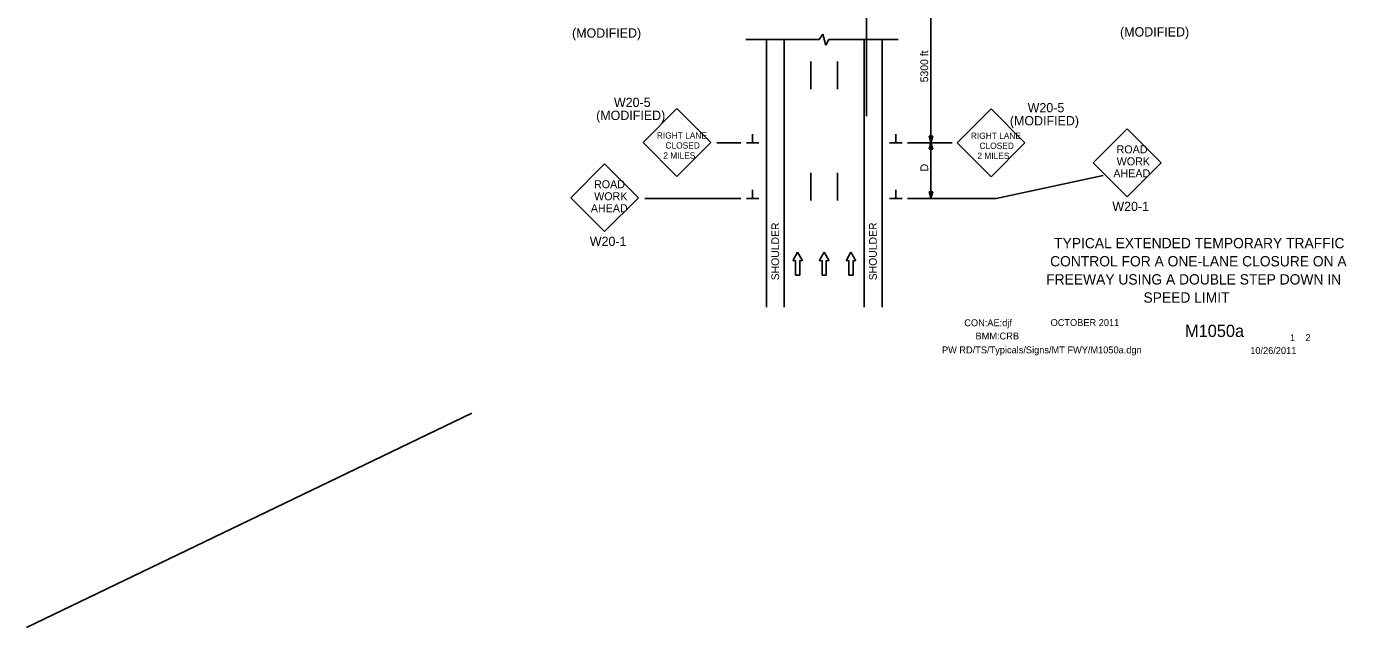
# Model space of a CAD drawing. Extents: x 16247 to 18479, y 5687 to 6964.
# Drawn here: x 16247 to 17435, y 5687 to 6228 of the extents above; entities that cross this region are included whole.
import ezdxf

# ---------------------------------------------------------------- set-up
doc = ezdxf.new("R2010")
doc.units = 0
for name, color, linetype in [('ALI_LEGAL_EX', 7, 'Continuous'), ('BORDER', 7, 'Continuous'), ('BORDER_SIGNAL_WO', 7, 'Continuous'), ('MT_SCRATCH_LEVEL_E', 7, 'Continuous'), ('PAVT_EDGE_EX', 7, 'Continuous'), ('TRAFFIC_SIGNS_PR', 7, 'Continuous'), ('TYPICAL_TEXT_DIMEN_PR', 7, 'Continuous')]:
    doc.layers.add(name, color=color, linetype=linetype)

msp = doc.modelspace()

# ---------------------------------------------------------------- linework, layer by layer
at = {"layer": 'ALI_LEGAL_EX'}
msp.add_line((17002.7, 6964.1), (17002.7, 6147.1), dxfattribs=at)
for points in [[(16952.7, 6196.2), (16952.7, 6171.2)], [(16976.7, 6196.2), (16976.7, 6171.2)], [(16952.7, 6096.2), (16952.7, 6071.2)], [(16976.7, 6096.2), (16976.7, 6071.2)]]:
    msp.add_lwpolyline(points, dxfattribs=at)
at = {"layer": 'MT_SCRATCH_LEVEL_E'}
for p, q in [((16940.7, 6024.8), (16936.6, 6017.6)), ((16944.9, 6017.6), (16940.7, 6024.8)), ((16964.6, 6024.8), (16960.5, 6017.6)), ((16968.8, 6017.6), (16964.6, 6024.8)), ((16988.7, 6024.8), (16984.6, 6017.6)), ((16992.8, 6017.6), (16988.7, 6024.8)), ((16937.1, 6016.9), (16938.9, 6017.2)), ((16938.9, 6017.2), (16938.9, 6003.9)), ((16942.6, 6003.9), (16942.6, 6017.2)), ((16942.6, 6017.2), (16944.4, 6016.9)), ((16961, 6016.9), (16962.8, 6017.2)), ((16962.8, 6017.2), (16962.8, 6003.9)), ((16966.5, 6003.9), (16966.5, 6017.2)), ((16966.5, 6017.2), (16968.3, 6016.9)), ((16985, 6016.9), (16986.8, 6017.2)), ((16986.8, 6017.2), (16986.8, 6003.9)), ((16990.6, 6003.9), (16990.6, 6017.2)), ((16990.6, 6017.2), (16992.3, 6016.9)), ((16938.9, 6003.9), (16942.6, 6003.9)), ((16962.8, 6003.9), (16966.5, 6003.9)), ((16986.8, 6003.9), (16990.6, 6003.9))]:
    msp.add_line(p, q, dxfattribs=at)
for centre, start, end in [((16937, 6017.4), 150.4248, 279.9638), ((16944.5, 6017.4), 260.0362, 29.7731), ((16960.9, 6017.4), 150.4248, 279.9638), ((16968.4, 6017.4), 260.0362, 29.7731), ((16985, 6017.4), 150.4248, 279.9638), ((16992.4, 6017.4), 260.0362, 29.7731)]:
    msp.add_arc(centre, 0.463, start, end, dxfattribs=at)
at = {"layer": 'PAVT_EDGE_EX'}
for p, q in [((16912.7, 6216.1), (16912.7, 5975.2)), ((16928.7, 6216.1), (16928.7, 5975.2)), ((17000.7, 6216.1), (17000.7, 5975.2)), ((17016.7, 6216.1), (17016.7, 5975.2))]:
    msp.add_line(p, q, dxfattribs=at)
at = {"layer": 'TRAFFIC_SIGNS_PR'}
for p, q in [((16832.2, 6153.9), (16801.7, 6123.3)), ((16862.7, 6123.3), (16832.2, 6153.9)), ((17114.8, 6153.6), (17084.2, 6123.1)), ((17145.3, 6123.1), (17114.8, 6153.6)), ((17237.2, 6135.7), (17206.7, 6105.1)), ((17267.8, 6105.1), (17237.2, 6135.7)), ((16801.7, 6123.3), (16832.2, 6092.8)), ((16832.2, 6092.8), (16862.7, 6123.3)), ((17084.2, 6123.1), (17114.8, 6092.5)), ((17114.8, 6092.5), (17145.3, 6123.1)), ((17206.7, 6105.1), (17237.2, 6074.6)), ((17237.2, 6074.6), (17267.8, 6105.1)), ((16767.1, 6104.3), (16736.6, 6073.7)), ((16797.7, 6073.7), (16767.1, 6104.3)), ((16736.6, 6073.7), (16767.1, 6043.2)), ((16767.1, 6043.2), (16797.7, 6073.7))]:
    msp.add_line(p, q, dxfattribs=at)
at = {"layer": 'TYPICAL_TEXT_DIMEN_PR'}
for p, q in [((17060.7, 6273.1), (17060.7, 6123.1)), ((16960.1, 6216.1), (16894.1, 6216.1)), ((16963.3, 6220.9), (16960.1, 6216.1)), ((16966.1, 6210.9), (16963.3, 6220.9)), ((16968.8, 6216.1), (16966.1, 6210.9)), ((17031.1, 6216.1), (16968.8, 6216.1)), ((16900.3, 6123.1), (16900.3, 6130.9)), ((17029.1, 6123.1), (17029.1, 6130.9)), ((17060.7, 6123.1), (17059.1, 6129)), ((17059.1, 6129), (17060.7, 6129)), ((17060.7, 6129), (17062.3, 6129)), ((17062.3, 6129), (17060.7, 6123.1)), ((16868, 6123.1), (16889.7, 6123.1)), ((16894.7, 6123.1), (16906, 6123.1)), ((17034.7, 6123.1), (17023.5, 6123.1)), ((17079.8, 6123.1), (17039.7, 6123.1)), ((17059.1, 6117.3), (17060.7, 6123.1)), ((17060.7, 6117.3), (17059.1, 6117.3)), ((17060.7, 6123.1), (17060.7, 6073.1)), ((17060.7, 6123.1), (17062.3, 6117.3)), ((17062.3, 6117.3), (17060.7, 6117.3)), ((17119.5, 6073.1), (17215.7, 6093.6)), ((16803.3, 6073.1), (16889.7, 6073.1)), ((16894.7, 6073.1), (16906, 6073.1)), ((16900.3, 6073.1), (16900.3, 6080.9)), ((17034.7, 6073.1), (17023.5, 6073.1)), ((17029.1, 6073.1), (17029.1, 6080.9)), ((17119.5, 6073.1), (17039.7, 6073.1)), ((17060.7, 6073.1), (17059.1, 6079)), ((17059.1, 6079), (17060.7, 6079)), ((17060.7, 6079), (17062.3, 6079)), ((17062.3, 6079), (17060.7, 6073.1)), ((16647.8, 5880), (16246.9, 5687))]:
    msp.add_line(p, q, dxfattribs=at)

# ---------------------------------------------------------------- texts
at = {"layer": 'BORDER'}
for s, p in [('TYPICAL EXTENDED TEMPORARY TRAFFIC', (17171.5, 6028.2)), ('CONTROL FOR A ONE-LANE CLOSURE ON A', (17167.9, 6011.9)), (' FREEWAY USING A DOUBLE STEP DOWN IN ', (17160.9, 5995.6)), ('SPEED LIMIT', (17251.9, 5979.3))]:
    msp.add_text(s, height=9.3, dxfattribs=at).set_placement(p)
at = {"layer": 'BORDER_SIGNAL_WO'}
for s, height, p in [('CON:AE:djf  ', 6.2, (17090.7, 5958.1)), ('    OCTOBER 2011    ', 6.2, (17159.1, 5958.3)), ('BMM:CRB   ', 6.2, (17100.8, 5946.2)), ('    M1050a   ', 11, (17272.9, 5948.4)), (' 1    2 ', 6.2, (17381.4, 5944.7)), ('PW RD/TS/Typicals/Signs/MT FWY/M1050a.dgn      ', 6.2, (17070.6, 5933.7)), ('10/26/2011    ', 6.2, (17347.9, 5933.1))]:
    msp.add_text(s, height=height, dxfattribs=at).set_placement(p)
at = {"layer": 'TRAFFIC_SIGNS_PR'}
for s, height, p in [('(MODIFIED)', 8.37, (16737.8, 6217.7)), ('(MODIFIED)', 8.37, (17230.8, 6218.7)), ('(MODIFIED)', 8.37, (16759.5, 6143.6)), ('W20-5', 8.37, (16775.5, 6155.3)), ('W20-5', 8.37, (17147.7, 6150.5)), ('(MODIFIED)', 8.37, (17131.7, 6138.8)), ('RIGHT LANE', 5.62, (16814.1, 6126.9)), ('RIGHT LANE', 5.62, (17096.6, 6126.6)), ('CLOSED', 5.62, (16821.9, 6117.9)), ('CLOSED', 5.62, (17104.4, 6117.6)), ('ROAD', 7.2, (17227.7, 6113.6)), ('2 MILES', 5.62, (16819.9, 6108.9)), ('2 MILES', 5.62, (17102.5, 6108.6)), ('WORK', 7.2, (17227.8, 6102.8)), ('AHEAD', 7.2, (17224.8, 6092)), ('ROAD', 7.2, (16757.6, 6082.2)), ('WORK', 7.2, (16757.7, 6071.4)), ('W20-1', 8.37, (17223.9, 6061.7)), ('AHEAD', 7.2, (16754.7, 6060.6)), ('W20-1', 8.37, (16753.8, 6030.3))]:
    msp.add_text(s, height=height, dxfattribs=at).set_placement(p)
at = {"layer": 'TYPICAL_TEXT_DIMEN_PR'}
for s, p in [('5300 ft', (17058.2, 6177.5)), ('D', (17058.2, 6097.4)), ('SHOULDER', (16924.1, 5999.4)), ('SHOULDER', (17012, 5999.4))]:
    msp.add_text(s, height=7, rotation=90, dxfattribs=at).set_placement(p)

doc.saveas('drawing.dxf')
